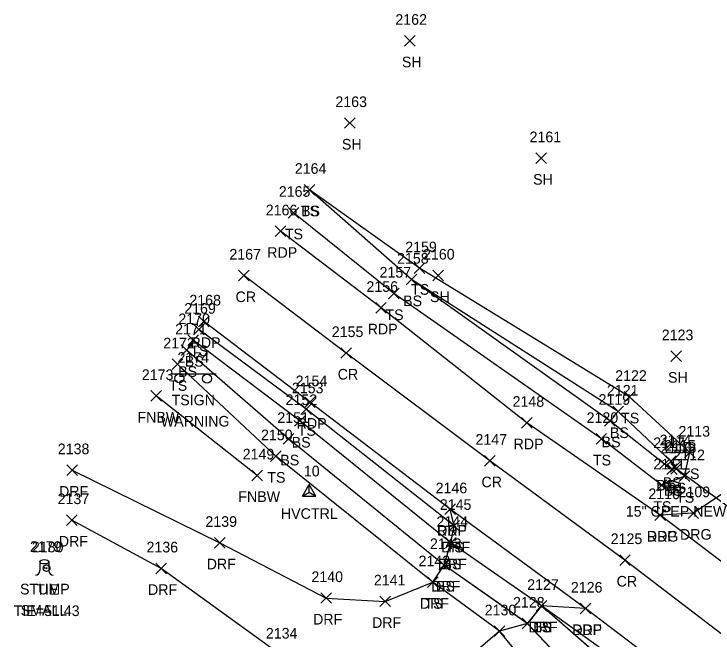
# Model space of a CAD drawing. Extents: x 1415642 to 1422021, y 544543 to 547232.
# Drawn here: x 1415641.7 to 1415773.3, y 547114.3 to 547232 of the extents above; entities that cross this region are included whole.
import ezdxf

# ---------------------------------------------------------------- set-up
doc = ezdxf.new("R2010")
doc.units = 0
for name, color, linetype in [('C_A', 7, 'Continuous'), ('C_C', 7, 'Continuous'), ('C_I', 7, 'Continuous'), ('CBP', 7, 'Continuous'), ('CPSM', 7, 'Continuous'), ('D_A', 7, 'Continuous'), ('D_C', 7, 'Continuous'), ('D_I', 7, 'Continuous'), ('D_TIC', 7, 'Continuous'), ('DCP', 7, 'Continuous'), ('L_A', 7, 'Continuous'), ('L_C', 7, 'Continuous'), ('L_I', 7, 'Continuous'), ('L_TIC', 7, 'Continuous'), ('LELB', 7, 'Continuous'), ('LFNC', 7, 'Continuous'), ('LTS', 7, 'Continuous'), ('P_A', 7, 'Continuous'), ('P_I', 7, 'Continuous'), ('P_TIC', 7, 'Continuous'), ('PET', 7, 'Continuous'), ('PRC', 7, 'Continuous'), ('R_A', 7, 'Continuous'), ('R_I', 7, 'Continuous'), ('R_TIC', 7, 'Continuous'), ('RDF', 7, 'Continuous'), ('RDG', 7, 'Continuous'), ('S_A', 7, 'Continuous'), ('S_C', 7, 'Continuous'), ('S_I', 7, 'Continuous'), ('SSGN', 7, 'Continuous')]:
    doc.layers.add(name, color=color, linetype=linetype)

msp = doc.modelspace()

# ---------------------------------------------------------------- linework, layer by layer
at = {"layer": 'CBP'}
for radius in [0.625, 0.0833]:
    msp.add_circle((1415647.85, 547127.6), radius, dxfattribs=at)
at = {"layer": 'CPSM'}
for p, q in [((1415696, 547141.18), (1415697.25, 547143.35)), ((1415698.5, 547141.18), (1415697.25, 547143.35)), ((1415697.25, 547141.9), (1415697.25, 547143.35)), ((1415696, 547141.18), (1415697.25, 547141.9)), ((1415697.25, 547141.9), (1415697.25, 547141.9)), ((1415697.25, 547141.9), (1415698.5, 547141.18)), ((1415696, 547141.18), (1415698.5, 547141.18))]:
    msp.add_line(p, q, dxfattribs=at)
at = {"layer": 'D_TIC'}
for points in [[(1415765.34, 547145.32), (1415767.34, 547147.32)], [(1415767.34, 547145.32), (1415765.34, 547147.32)]]:
    msp.add_lwpolyline(points, dxfattribs=at)
at = {"layer": 'DCP'}
msp.add_lwpolyline([(1415790.67, 547128.55), (1415766.34, 547146.32)], dxfattribs=at)
msp.add_lwpolyline([(1415790.67, 547128.55), (1415766.34, 547146.32)], dxfattribs=at)
at = {"layer": 'L_TIC'}
for points in [[(1415715.24, 547225.93), (1415717.24, 547227.93)], [(1415717.24, 547225.93), (1415715.24, 547227.93)], [(1415703.95, 547210.44), (1415705.95, 547212.44)], [(1415705.95, 547210.44), (1415703.95, 547212.44)], [(1415739.94, 547203.82), (1415741.94, 547205.82)], [(1415741.94, 547203.82), (1415739.94, 547205.82)], [(1415696.31, 547197.87), (1415698.31, 547199.87)], [(1415698.31, 547197.87), (1415696.31, 547199.87)], [(1415696.31, 547197.87), (1415698.31, 547199.87)], [(1415698.31, 547197.87), (1415696.31, 547199.87)], [(1415693.3, 547193.54), (1415695.3, 547195.54)], [(1415695.3, 547193.54), (1415693.3, 547195.54)], [(1415717.06, 547183.1), (1415719.06, 547185.1)], [(1415719.06, 547183.1), (1415717.06, 547185.1)], [(1415720.54, 547181.72), (1415722.54, 547183.72)], [(1415722.54, 547181.72), (1415720.54, 547183.72)], [(1415715.52, 547180.95), (1415717.52, 547182.95)], [(1415717.52, 547180.95), (1415715.52, 547182.95)], [(1415715.52, 547180.95), (1415717.52, 547182.95)], [(1415717.52, 547180.95), (1415715.52, 547182.95)], [(1415712.22, 547178.33), (1415714.22, 547180.33)], [(1415714.22, 547178.33), (1415712.22, 547180.33)], [(1415675.49, 547171.53), (1415677.49, 547173.53)], [(1415677.49, 547171.53), (1415675.49, 547173.53)], [(1415674.42, 547169.57), (1415676.42, 547171.57)], [(1415676.42, 547169.57), (1415674.42, 547171.57)], [(1415673.17, 547167.64), (1415675.17, 547169.64)], [(1415675.17, 547167.64), (1415673.17, 547169.64)], [(1415765.35, 547166.54), (1415767.35, 547168.54)], [(1415767.35, 547166.54), (1415765.35, 547168.54)], [(1415671.49, 547165.01), (1415673.49, 547167.01)], [(1415673.49, 547165.01), (1415671.49, 547167.01)], [(1415667.46, 547159.04), (1415669.46, 547161.04)], [(1415669.46, 547159.04), (1415667.46, 547161.04)], [(1415756.59, 547158.88), (1415758.59, 547160.88)], [(1415758.59, 547158.88), (1415756.59, 547160.88)], [(1415695.71, 547156.55), (1415697.71, 547158.55)], [(1415697.71, 547156.55), (1415695.71, 547158.55)], [(1415754.45, 547156.12), (1415756.45, 547158.12)], [(1415756.45, 547156.12), (1415754.45, 547158.12)], [(1415694.54, 547154.33), (1415696.54, 547156.33)], [(1415696.54, 547154.33), (1415694.54, 547156.33)], [(1415752.89, 547154.38), (1415754.89, 547156.38)], [(1415754.89, 547154.38), (1415752.89, 547156.38)], [(1415692.4, 547150.97), (1415694.4, 547152.97)], [(1415694.4, 547150.97), (1415692.4, 547152.97)], [(1415751.28, 547150.96), (1415753.28, 547152.96)], [(1415753.28, 547150.96), (1415751.28, 547152.96)], [(1415689.99, 547147.71), (1415691.99, 547149.71)], [(1415691.99, 547147.71), (1415689.99, 547149.71)], [(1415767.93, 547148.39), (1415769.93, 547150.39)], [(1415769.93, 547148.39), (1415767.93, 547150.39)], [(1415763.18, 547146.23), (1415765.18, 547148.23)], [(1415765.18, 547146.23), (1415763.18, 547148.23)], [(1415764.39, 547146.74), (1415766.39, 547148.74)], [(1415766.39, 547146.74), (1415764.39, 547148.74)], [(1415764.39, 547146.74), (1415766.39, 547148.74)], [(1415766.39, 547146.74), (1415764.39, 547148.74)], [(1415764.58, 547145.24), (1415766.58, 547147.24)], [(1415766.58, 547145.24), (1415764.58, 547147.24)], [(1415765.21, 547145.72), (1415767.21, 547147.72)], [(1415767.21, 547145.72), (1415765.21, 547147.72)], [(1415686.46, 547144.09), (1415688.46, 547146.09)], [(1415688.46, 547144.09), (1415686.46, 547146.09)], [(1415766.95, 547143.94), (1415768.95, 547145.94)], [(1415768.95, 547143.94), (1415766.95, 547145.94)], [(1415762.64, 547142.22), (1415764.64, 547144.22)], [(1415764.64, 547142.22), (1415762.64, 547144.22)], [(1415762.64, 547142.22), (1415764.64, 547144.22)], [(1415764.64, 547142.22), (1415762.64, 547144.22)], [(1415723.56, 547134.59), (1415725.56, 547136.59)], [(1415725.56, 547134.59), (1415723.56, 547136.59)], [(1415722.94, 547131.39), (1415724.94, 547133.39)], [(1415724.94, 547131.39), (1415722.94, 547133.39)], [(1415721.7, 547127.21), (1415723.7, 547129.21)], [(1415723.7, 547127.21), (1415721.7, 547129.21)], [(1415719.57, 547123.98), (1415721.57, 547125.98)], [(1415721.57, 547123.98), (1415719.57, 547125.98)], [(1415740.01, 547119.53), (1415742.01, 547121.53)], [(1415742.01, 547119.53), (1415740.01, 547121.53)], [(1415740.01, 547119.53), (1415742.01, 547121.53)], [(1415742.01, 547119.53), (1415740.01, 547121.53)], [(1415737.35, 547116.19), (1415739.35, 547118.19)], [(1415739.35, 547116.19), (1415737.35, 547118.19)], [(1415732.1, 547114.73), (1415734.1, 547116.73)], [(1415734.1, 547114.73), (1415732.1, 547116.73)]]:
    msp.add_lwpolyline(points, dxfattribs=at)
at = {"layer": 'LELB'}
for points in [[(1415763.64, 547143.22), (1415767.95, 547144.94), (1415768.93, 547149.39), (1415757.59, 547159.88), (1415718.06, 547184.1), (1415697.31, 547198.87)], [(1415765.39, 547147.74), (1415766.21, 547146.72), (1415765.58, 547146.24), (1415764.18, 547147.23), (1415753.89, 547155.38), (1415716.52, 547181.95), (1415697.31, 547198.87)], [(1415763.64, 547143.22), (1415767.95, 547144.94), (1415768.93, 547149.39), (1415757.58, 547159.88), (1415718.06, 547184.1), (1415697.31, 547198.86)], [(1415765.39, 547147.74), (1415766.21, 547146.72), (1415765.57, 547146.24), (1415764.17, 547147.23), (1415753.88, 547155.38), (1415716.52, 547181.95), (1415697.31, 547198.86)], [(1415763.64, 547143.22), (1415752.28, 547151.96), (1415713.22, 547179.33), (1415694.3, 547194.54)], [(1415763.64, 547143.22), (1415752.28, 547151.96), (1415713.22, 547179.33), (1415694.3, 547194.54)], [(1415765.39, 547147.74), (1415755.45, 547157.12), (1415716.52, 547181.95)], [(1415765.39, 547147.74), (1415755.46, 547157.12), (1415716.52, 547181.95)], [(1415724.56, 547135.59), (1415696.71, 547157.55), (1415676.49, 547172.53)], [(1415724.56, 547135.59), (1415696.71, 547157.55), (1415676.49, 547172.53)], [(1415821.69, 547055.02), (1415783.27, 547083.61), (1415741.01, 547120.53), (1415723.94, 547132.39), (1415695.54, 547155.33), (1415675.42, 547170.57)], [(1415821.7, 547055.02), (1415783.28, 547083.61), (1415741.01, 547120.53), (1415723.94, 547132.38), (1415695.54, 547155.33), (1415675.42, 547170.56)], [(1415851.29, 546999.16), (1415835.48, 547016.01), (1415808.9, 547044.81), (1415779.47, 547073.63), (1415738.35, 547117.19), (1415722.7, 547128.21), (1415693.4, 547151.97), (1415674.17, 547168.64)], [(1415851.29, 546999.15), (1415835.48, 547016.02), (1415808.9, 547044.81), (1415779.47, 547073.63), (1415738.34, 547117.19), (1415722.7, 547128.21), (1415693.4, 547151.96), (1415674.17, 547168.64)], [(1415802.21, 547036.19), (1415775.31, 547066.85), (1415750.83, 547094.22), (1415733.1, 547115.73), (1415720.57, 547124.98), (1415690.99, 547148.71), (1415672.49, 547166.01)], [(1415802.2, 547036.19), (1415775.31, 547066.86), (1415750.83, 547094.23), (1415733.1, 547115.73), (1415720.57, 547124.98), (1415690.99, 547148.71), (1415672.49, 547166.01)], [(1415979.27, 546932.57), (1415964.6, 546940.59), (1415957.63, 546956.7), (1415934.73, 546972.98), (1415912.21, 546991.17), (1415886.95, 547011.09), (1415854.08, 547036.67), (1415824.18, 547059.44), (1415786.82, 547087.62), (1415741.01, 547120.53)], [(1415979.28, 546932.57), (1415964.61, 546940.59), (1415957.63, 546956.7), (1415934.74, 546972.98), (1415912.22, 546991.17), (1415886.96, 547011.09), (1415854.08, 547036.67), (1415824.19, 547059.44), (1415786.82, 547087.62), (1415741.01, 547120.53)]]:
    msp.add_lwpolyline(points, dxfattribs=at)
at = {"layer": 'LFNC'}
msp.add_lwpolyline([(1415687.46, 547145.09), (1415668.46, 547160.04)], dxfattribs=at)
msp.add_lwpolyline([(1415687.46, 547145.09), (1415668.46, 547160.04)], dxfattribs=at)
at = {"layer": 'LTS'}
for p, q in [((1415646.59, 547128.82), (1415646.59, 547127.15)), ((1415648.25, 547128.65), (1415648.25, 547128.82)), ((1415648.25, 547128.82), (1415648.25, 547127.15)), ((1415647.42, 547127.68), (1415647.42, 547127.68)), ((1415647.42, 547127.68), (1415647.42, 547127.68)), ((1415647.42, 547127.65), (1415647.42, 547127.65))]:
    msp.add_line(p, q, dxfattribs=at)
msp.add_circle((1415647.42, 547127.68), 0.0833, dxfattribs=at)
for centre, start, end in [((1415645.75, 547127.15), 270, 360), ((1415649.09, 547127.15), 180, 270)]:
    msp.add_arc(centre, 0.833, start, end, dxfattribs=at)
msp.add_ellipse((1415647.42, 547128.82), major_axis=(-0.833, 0), ratio=0.5, dxfattribs=at)
at = {"layer": 'P_TIC'}
for points in [[(1415690.9, 547190.05), (1415692.9, 547192.05)], [(1415692.9, 547190.05), (1415690.9, 547192.05)], [(1415683.99, 547181.72), (1415685.99, 547183.72)], [(1415685.99, 547181.72), (1415683.99, 547183.72)], [(1415709.8, 547175.64), (1415711.8, 547177.64)], [(1415711.8, 547175.64), (1415709.8, 547177.64)], [(1415676.46, 547173.08), (1415678.46, 547175.08)], [(1415678.46, 547173.08), (1415676.46, 547175.08)], [(1415703.22, 547167.13), (1415705.22, 547169.13)], [(1415705.22, 547167.13), (1415703.22, 547169.13)], [(1415696.43, 547157.88), (1415698.43, 547159.88)], [(1415698.43, 547157.88), (1415696.43, 547159.88)], [(1415737.26, 547154), (1415739.26, 547156)], [(1415739.26, 547154), (1415737.26, 547156)], [(1415730.28, 547146.85), (1415732.28, 547148.85)], [(1415732.28, 547146.85), (1415730.28, 547148.85)], [(1415722.83, 547137.72), (1415724.83, 547139.72)], [(1415724.83, 547137.72), (1415722.83, 547139.72)], [(1415762.35, 547136.62), (1415764.35, 547138.62)], [(1415764.35, 547136.62), (1415762.35, 547138.62)], [(1415755.73, 547128.15), (1415757.73, 547130.15)], [(1415757.73, 547128.15), (1415755.73, 547130.15)], [(1415748.29, 547119.02), (1415750.29, 547121.02)], [(1415750.29, 547119.02), (1415748.29, 547121.02)]]:
    msp.add_lwpolyline(points, dxfattribs=at)
at = {"layer": 'PET'}
for points in [[(1415969.06, 546981.93), (1415936.64, 547006.92), (1415904.27, 547031.49), (1415869.9, 547057.78), (1415840.56, 547080.38), (1415803.16, 547107.61), (1415784.15, 547121.85), (1415763.35, 547137.62), (1415738.26, 547155), (1415710.8, 547176.64), (1415691.9, 547191.05)], [(1415969.07, 546981.93), (1415936.65, 547006.92), (1415904.27, 547031.49), (1415869.9, 547057.78), (1415840.56, 547080.38), (1415803.16, 547107.61), (1415784.15, 547121.85), (1415763.35, 547137.62), (1415738.26, 547155), (1415710.8, 547176.64), (1415691.9, 547191.04)], [(1415982.21, 546942.39), (1415954.4, 546964.56), (1415923.45, 546987.94), (1415890.93, 547013.5), (1415855.69, 547039.7), (1415826.51, 547062.15), (1415788.27, 547090.37), (1415749.29, 547120.02), (1415723.83, 547138.72), (1415697.43, 547158.88), (1415677.46, 547174.08)], [(1415982.21, 546942.39), (1415954.4, 546964.56), (1415923.45, 546987.94), (1415890.93, 547013.5), (1415855.69, 547039.7), (1415826.51, 547062.15), (1415788.27, 547090.37), (1415749.28, 547120.03), (1415723.83, 547138.72), (1415697.43, 547158.88), (1415677.46, 547174.08)]]:
    msp.add_lwpolyline(points, dxfattribs=at)
at = {"layer": 'PRC'}
for points in [[(1415989.92, 546951.68), (1415962.46, 546973.18), (1415930.15, 546997.68), (1415898.02, 547022.56), (1415862.93, 547049.07), (1415833.82, 547071.85), (1415795.61, 547099.36), (1415756.73, 547129.15), (1415731.28, 547147.85), (1415704.22, 547168.12), (1415684.99, 547182.73)], [(1415989.92, 546951.67), (1415962.46, 546973.18), (1415930.15, 546997.68), (1415898.02, 547022.56), (1415862.93, 547049.07), (1415833.81, 547071.85), (1415795.61, 547099.36), (1415756.73, 547129.15), (1415731.28, 547147.85), (1415704.22, 547168.13), (1415684.99, 547182.72)]]:
    msp.add_lwpolyline(points, dxfattribs=at)
at = {"layer": 'R_TIC'}
for points in [[(1415651.64, 547145.08), (1415653.64, 547147.08)], [(1415653.64, 547145.08), (1415651.64, 547147.08)], [(1415722.83, 547137.72), (1415724.83, 547139.72)], [(1415724.83, 547137.72), (1415722.83, 547139.72)], [(1415768.6, 547136.98), (1415770.6, 547138.98)], [(1415770.6, 547136.98), (1415768.6, 547138.98)], [(1415651.61, 547135.68), (1415653.61, 547137.68)], [(1415653.61, 547135.68), (1415651.61, 547137.68)], [(1415762.35, 547136.62), (1415764.35, 547138.62)], [(1415764.35, 547136.62), (1415762.35, 547138.62)], [(1415723.56, 547134.59), (1415725.56, 547136.59)], [(1415725.56, 547134.59), (1415723.56, 547136.59)], [(1415679.44, 547131.4), (1415681.44, 547133.4)], [(1415681.44, 547131.4), (1415679.44, 547133.4)], [(1415722.94, 547131.39), (1415724.94, 547133.39)], [(1415724.94, 547131.39), (1415722.94, 547133.39)], [(1415668.4, 547126.58), (1415670.4, 547128.58)], [(1415670.4, 547126.58), (1415668.4, 547128.58)], [(1415721.7, 547127.21), (1415723.7, 547129.21)], [(1415723.7, 547127.21), (1415721.7, 547129.21)], [(1415719.57, 547123.98), (1415721.57, 547125.98)], [(1415721.57, 547123.98), (1415719.57, 547125.98)], [(1415699.48, 547121), (1415701.48, 547123)], [(1415701.48, 547121), (1415699.48, 547123)], [(1415710.57, 547120.37), (1415712.57, 547122.37)], [(1415712.57, 547120.37), (1415710.57, 547122.37)], [(1415740.01, 547119.53), (1415742.01, 547121.53)], [(1415742.01, 547119.53), (1415740.01, 547121.53)], [(1415748.29, 547119.02), (1415750.29, 547121.02)], [(1415750.29, 547119.02), (1415748.29, 547121.02)], [(1415737.35, 547116.19), (1415739.35, 547118.19)], [(1415739.35, 547116.19), (1415737.35, 547118.19)], [(1415732.1, 547114.73), (1415734.1, 547116.73)], [(1415734.1, 547114.73), (1415732.1, 547116.73)]]:
    msp.add_lwpolyline(points, dxfattribs=at)
at = {"layer": 'RDF'}
for points in [[(1415652.64, 547146.08), (1415680.44, 547132.4), (1415700.48, 547122), (1415711.57, 547121.37), (1415720.57, 547124.98), (1415722.7, 547128.21), (1415723.94, 547132.39), (1415724.56, 547135.59), (1415723.83, 547138.72)], [(1415652.65, 547146.08), (1415680.44, 547132.4), (1415700.48, 547122), (1415711.57, 547121.37), (1415720.57, 547124.98), (1415722.7, 547128.21), (1415723.94, 547132.38), (1415724.56, 547135.59), (1415723.83, 547138.72)], [(1415749.29, 547120.02), (1415741.01, 547120.53), (1415738.35, 547117.19), (1415733.1, 547115.73), (1415714.02, 547099.39), (1415691.81, 547111.36), (1415669.4, 547127.58), (1415652.61, 547136.68)], [(1415749.28, 547120.03), (1415741.01, 547120.53), (1415738.34, 547117.19), (1415733.1, 547115.73), (1415714.01, 547099.4), (1415691.81, 547111.36), (1415669.4, 547127.58), (1415652.61, 547136.68)]]:
    msp.add_lwpolyline(points, dxfattribs=at)
at = {"layer": 'RDG'}
msp.add_lwpolyline([(1415802.37, 547156.61), (1415783.3, 547147.13), (1415769.6, 547137.98), (1415763.35, 547137.62)], dxfattribs=at)
msp.add_lwpolyline([(1415802.37, 547156.61), (1415783.3, 547147.13), (1415769.6, 547137.98), (1415763.35, 547137.62)], dxfattribs=at)
at = {"layer": 'SSGN'}
for p, q in [((1415671.17, 547164.2), (1415679.77, 547164.2)), ((1415675.19, 547163.29), (1415675.19, 547163.29))]:
    msp.add_line(p, q, dxfattribs=at)
for centre in [(1415672.83, 547163.36), (1415678.04, 547163.29)]:
    msp.add_circle(centre, 0.833, dxfattribs=at)

# ---------------------------------------------------------------- texts
at = {"layer": 'C_A'}
for s, p in [('HVCTRL', (1415691.95, 547136.9)), ('TIE', (1415645.92, 547122.6))]:
    msp.add_text(s, height=2, dxfattribs=at).set_placement(p)
at = {"layer": 'C_C'}
msp.add_text('TIE=51.43', height=2, dxfattribs=at).set_placement((1415641.64, 547118.6))
at = {"layer": 'C_I'}
for s, p in [('10', (1415696.27, 547144.9)), ('2180', (1415645.07, 547130.6))]:
    msp.add_text(s, height=2, dxfattribs=at).set_placement(p)
at = {"layer": 'D_A'}
msp.add_text('P', height=2, dxfattribs=at).set_placement((1415765.72, 547141.32))
at = {"layer": 'D_C'}
msp.add_text('15" CPEP NEW', height=2, dxfattribs=at).set_placement((1415756.88, 547137.32))
at = {"layer": 'D_I'}
msp.add_text('2118', height=2, dxfattribs=at).set_placement((1415764.22, 547149.32))
at = {"layer": 'L_A'}
for s, p in [('SH', (1415714.73, 547221.93)), ('SH', (1415703.44, 547206.44)), ('SH', (1415739.43, 547199.82)), ('TS', (1415695.72, 547193.87)), ('BS', (1415695.75, 547193.87)), ('TS', (1415692.7, 547189.54)), ('TS', (1415716.47, 547179.1)), ('SH', (1415720.02, 547177.72)), ('BS', (1415714.96, 547176.95)), ('BS', (1415714.96, 547176.95)), ('TS', (1415711.63, 547174.33)), ('TS', (1415674.9, 547167.53)), ('BS', (1415673.86, 547165.57)), ('BS', (1415672.61, 547163.64)), ('SH', (1415764.84, 547162.54)), ('TS', (1415670.9, 547161.01)), ('FNBW', (1415664.94, 547155.04)), ('TS', (1415756, 547154.88)), ('TS', (1415695.12, 547152.55)), ('BS', (1415753.9, 547152.12)), ('BS', (1415693.98, 547150.33)), ('BS', (1415752.33, 547150.38)), ('BS', (1415691.84, 547146.97)), ('TS', (1415750.69, 547146.96)), ('TS', (1415689.4, 547143.71)), ('TS', (1415767.34, 547144.39)), ('BS', (1415762.62, 547142.23)), ('BS', (1415763.83, 547142.74)), ('BS', (1415763.83, 547142.74)), ('BS', (1415764.02, 547141.24)), ('BS', (1415764.65, 547141.72)), ('FNBW', (1415683.93, 547140.09)), ('TS', (1415766.36, 547139.94)), ('TS', (1415762.05, 547138.22)), ('TS', (1415762.05, 547138.22)), ('TS', (1415722.97, 547130.59)), ('BS', (1415722.38, 547127.39)), ('STUMP', (1415642.84, 547122.68)), ('BS', (1415721.14, 547123.21)), ('TS', (1415718.98, 547119.98)), ('TS', (1415739.42, 547115.53)), ('BS', (1415739.45, 547115.53))]:
    msp.add_text(s, height=2, dxfattribs=at).set_placement(p)
at = {"layer": 'L_C'}
msp.add_text('SMALL', height=2, dxfattribs=at).set_placement((1415642.96, 547118.68))
at = {"layer": 'L_I'}
for s, p in [('2162', (1415713.5, 547229.93)), ('2163', (1415702.21, 547214.44)), ('2161', (1415738.77, 547207.82)), ('2164', (1415694.57, 547201.87)), ('2164', (1415694.57, 547201.87)), ('2165', (1415691.56, 547197.54)), ('2159', (1415715.36, 547187.1)), ('2160', (1415718.71, 547185.72)), ('2158', (1415713.82, 547184.95)), ('2158', (1415713.82, 547184.95)), ('2157', (1415710.52, 547182.33)), ('2169', (1415673.75, 547175.53)), ('2170', (1415672.64, 547173.57)), ('2171', (1415672.04, 547171.64)), ('2123', (1415763.66, 547170.54)), ('2172', (1415669.8, 547169.01)), ('2173', (1415665.77, 547163.04)), ('2122', (1415754.89, 547162.88)), ('2153', (1415694.02, 547160.55)), ('2121', (1415753.33, 547160.12)), ('2152', (1415692.84, 547158.33)), ('2119', (1415751.75, 547158.38)), ('2151', (1415691.28, 547154.97)), ('2120', (1415749.5, 547154.96)), ('2150', (1415688.21, 547151.71)), ('2113', (1415766.8, 547152.39)), ('2117', (1415762.05, 547150.23)), ('2114', (1415763.26, 547150.74)), ('2114', (1415763.26, 547150.74)), ('2116', (1415763.4, 547149.24)), ('2115', (1415764.09, 547149.72)), ('2149', (1415684.76, 547148.09)), ('2112', (1415765.83, 547147.94)), ('2111', (1415762.08, 547146.22)), ('2111', (1415762.08, 547146.22)), ('2145', (1415721.87, 547138.59)), ('2144', (1415721.25, 547135.39)), ('2179', (1415644.71, 547130.68)), ('2143', (1415720.01, 547131.21)), ('2142', (1415717.87, 547127.98)), ('2127', (1415738.32, 547123.53)), ('2127', (1415738.32, 547123.53)), ('2128', (1415735.65, 547120.19)), ('2130', (1415730.32, 547118.73))]:
    msp.add_text(s, height=2, dxfattribs=at).set_placement(p)
at = {"layer": 'P_A'}
for s, p in [('RDP', (1415689.38, 547186.05)), ('CR', (1415683.42, 547177.72)), ('RDP', (1415708.29, 547171.64)), ('RDP', (1415674.95, 547169.08)), ('CR', (1415702.65, 547163.13)), ('RDP', (1415694.92, 547153.88)), ('RDP', (1415735.75, 547150)), ('CR', (1415729.71, 547142.85)), ('RDP', (1415721.32, 547133.72)), ('RDP', (1415760.84, 547132.62)), ('CR', (1415755.16, 547124.15)), ('RDP', (1415746.77, 547115.02))]:
    msp.add_text(s, height=2, dxfattribs=at).set_placement(p)
at = {"layer": 'P_I'}
for s, p in [('2166', (1415689.1, 547194.05)), ('2167', (1415682.25, 547185.72)), ('2156', (1415708.06, 547179.64)), ('2168', (1415674.72, 547177.08)), ('2155', (1415701.53, 547171.13)), ('2154', (1415694.74, 547161.88)), ('2148', (1415735.57, 547158)), ('2147', (1415728.58, 547150.85)), ('2146', (1415721.08, 547141.72)), ('2110', (1415761.14, 547140.62)), ('2125', (1415754.04, 547132.15)), ('2126', (1415746.54, 547123.02))]:
    msp.add_text(s, height=2, dxfattribs=at).set_placement(p)
at = {"layer": 'R_A'}
for s, p in [('DRF', (1415650.18, 547141.08)), ('DRF', (1415721.36, 547133.72)), ('DRG', (1415767.09, 547132.98)), ('DRF', (1415650.14, 547131.68)), ('DRG', (1415760.84, 547132.62)), ('DRF', (1415722.1, 547130.59)), ('DRF', (1415677.98, 547127.4)), ('DRF', (1415721.47, 547127.39)), ('DRF', (1415666.93, 547122.58)), ('DRF', (1415720.24, 547123.21)), ('DRF', (1415718.1, 547119.98)), ('DRF', (1415698.01, 547117)), ('DRF', (1415709.11, 547116.37)), ('DRF', (1415738.55, 547115.53)), ('DRF', (1415746.82, 547115.02))]:
    msp.add_text(s, height=2, dxfattribs=at).set_placement(p)
at = {"layer": 'R_I'}
for s, p in [('2138', (1415649.95, 547149.08)), ('2146', (1415721.08, 547141.72)), ('2109', (1415766.82, 547140.98)), ('2137', (1415649.92, 547139.68)), ('2110', (1415761.14, 547140.62)), ('2145', (1415721.87, 547138.59)), ('2139', (1415677.74, 547135.4)), ('2144', (1415721.25, 547135.39)), ('2136', (1415666.65, 547130.58)), ('2143', (1415720.01, 547131.21)), ('2142', (1415717.87, 547127.98)), ('2140', (1415697.7, 547125)), ('2141', (1415709.45, 547124.37)), ('2127', (1415738.32, 547123.53)), ('2126', (1415746.54, 547123.02)), ('2128', (1415735.65, 547120.19)), ('2130', (1415730.32, 547118.73)), ('2134', (1415689.12, 547114.36))]:
    msp.add_text(s, height=2, dxfattribs=at).set_placement(p)
at = {"layer": 'S_A'}
msp.add_text('TSIGN', height=2, dxfattribs=at).set_placement((1415671.37, 547158.28))
at = {"layer": 'S_C'}
msp.add_text('WARNING', height=2, dxfattribs=at).set_placement((1415669.35, 547154.28))
at = {"layer": 'S_I'}
msp.add_text('2174', height=2, dxfattribs=at).set_placement((1415672.49, 547166.28))

doc.saveas('drawing.dxf')
